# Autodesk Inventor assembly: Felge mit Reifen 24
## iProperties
Shininess: 64.0
Length Units: 11269
Angle Units: 11279
Time Units: 11290
Mass Units: 11283
Length Display Precision: 3
Angle Display Precision: 2
Compacted: True
Created: 2003-10
Part Number: Felge mit Reifen 24
Document SubType Name: Assembly
Designer: Bernhard Fetzer
Manufacturer: Standard
Standards Organization: Custom
Density: 0.0
Volumn: 0.0
Area: 0.0
PropertySet Name: Model Information
Control State: 0
Master: False
Checked Out: False
Author: Bernhard Fetzer
